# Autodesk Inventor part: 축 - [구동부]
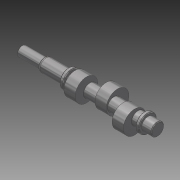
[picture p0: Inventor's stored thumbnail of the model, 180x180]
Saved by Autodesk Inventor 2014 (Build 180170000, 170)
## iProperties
Company: 한국ATC센터
Created: 2014-08
Part Number: 축 - [구동부]
Document SubType Name: Modeling
Designer: mdu
Density: 7.86 g/cm^3
Material: 강철, 연강
Mass: 484.347 g
Surface Area: 153.549 cm^2
Volume: 61.6218 cm^3
Appearance: 반광택
Author: mdu
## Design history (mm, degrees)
sketch "스케치1"
  geometry: L1 (-90.5, 0)-(90.5, 0); L2 (-90.5, 0)-(-90.5, 6.5); L3 (-58.681, 8.5)-(-28.5, 8.5); L4 (-28.5, 8.5)-(-28.5, 12); L5 (-28.5, 12)-(-23.5, 12); L6 (-23.5, 12)-(-23.5, 8.5); L7 (-23.5, 8.5)-(72.5, 8.5); L8 (72.5, 8.5)-(72.5, 12); L9 (72.5, 12)-(77.5, 12); L10 (77.5, 12)-(77.5, 8.5); L11 (77.5, 8.5)-(90.5, 8.5); L12 (90.5, 8.5)-(90.5, 0); L13 (-60.5, 7.45)-(-60.5, 6.5); L14 (-60.5, 6.5)-(-90.5, 6.5); L15 (-60.5, 7.45)-(-58.681, 8.5); 2 further points
  constraints: 30 end point, 6 parallel, 2 perpendicular, 1 coincident, 1 horizontal, 1 midpoint
  dimensions: "d0" = 181 distance of L1.start L1.end (derived); "d2" = 17 diameter of L3 L1; "d3" = 24 diameter of L5 L1; "d4" = 17 diameter of L7 L1; "d5" = 24 diameter of L9 L1; "d6" = 17 diameter of L11 L1; "d7" = 5 distance of L8.end L9.end; "d8" = 5 distance of L4.end L5.end; "d11" = 13 distance of L10.end L11.end; "d35" = 96 distance between parallel lines of L8 L6; "d57" = 13 diameter of L14 L1; "d58" = 62 distance between parallel lines of L4 L2; "d60" = 30 horizontal distance of L2.end L13.start; "d61" = 14.9 diameter of L13.start L1; "d62" = 30 deg angle of L3 L15
revolve "회전1" sketch "스케치1" stored, may be unused: angle "d12" = 90 deg
node "작업 평면7"
sketch "스케치6"
  geometry: C1 r 15 at (0, 5); 1 further point
  constraints: 1 centre point, 1 vertical alignment
  dimensions: "d37" = 30 diameter of C1; "d38" = 5 distance of C1.centre point (0, 0)
extrude "돌출4" join sketch "스케치6" stored distance "d33" = 15; taper "d34" = 0 deg
node "작업 평면8"
sketch "스케치7"
  geometry: L1 (0, 0)-(-6, -10.392); L2 (0, 0)-(12, 0); C1 r 15 at (-2.5, -4.33); A1 r 12 centre (0, 0) between (-6, -10.392) and (12, 0) reference; 1 further point
  constraints: 4 end point, 2 point on circle, 1 centre point, 1 horizontal, 1 point on line
  dimensions: "d40" = 120 deg angle of L1 L2; "d41" = 30 diameter of C1; "d42" = 5 distance of point (0, 0) C1.centre
extrude "돌출5" join sketch "스케치7" stored distance "d43" = 15; taper "d44" = 0 deg
node "작업 평면9"
sketch "스케치8"
  geometry: L1 (0, 0)-(4.25, -7.361); L2 (0, 0)-(-8.5, 0); C1 r 15 at (2.5, -4.33); A1 r 8.5 centre (0, 0) between (4.25, -7.361) and (-8.5, 0) reference; 1 further point
  constraints: 4 end point, 2 point on circle, 1 centre point, 1 horizontal, 1 point on line
  dimensions: "d46" = 120 deg angle of L1 L2; "d47" = 30 diameter of C1; "d48" = 5 distance of point (0, 0) C1.centre
extrude "돌출6" join sketch "스케치8" stored distance "d49" = 15; taper "d50" = 0 deg
node "작업 평면3"
sketch "스케치5"
  geometry: L1 (84, -2.5)-(71, -2.5); L2 (71, 2.5)-(84, 2.5); L3 (60.5, 7.45)-(60.5, -7.45) reference; A1 r 2.5 centre (71, 0) between (71, 2.5) and (71, -2.5); A2 r 2.5 centre (84, 0) between (84, -2.5) and (84, 2.5); 2 further points
  constraints: 4 end point, 4 point on circle, 4 tangent, 3 horizontal alignment, 2 centre point, 1 midpoint, 1 parallel
  dimensions: "d23" = 5 distance between parallel lines of L2 L1; "d67" = 18 dimension on A2 A1; "d68" = 8 distance edge to line of A1 L3
extrude "돌출3" cut sketch "스케치5" distance "d25" = 3; taper "d26" = 0 deg
chamfer "모따기1" distance "d27" = 1; stored, may be unused: second distance "d28" = 2, angle "d29" = 45 deg
fillet "모깎기1" dims "d51" = 0.3
chamfer "모따기2" distance "d53" = 1; stored, may be unused: second distance "d54" = 2, angle "d55" = 45 deg
node "작업 평면10"
fillet "모깎기2" dims "d63" = 4
fillet "모깎기3" dims "d64" = 1
node "솔리드1"
other parameters: "d39" = -32, "d45" = 32, "d66" = 6.5
